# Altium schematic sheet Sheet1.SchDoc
size A4
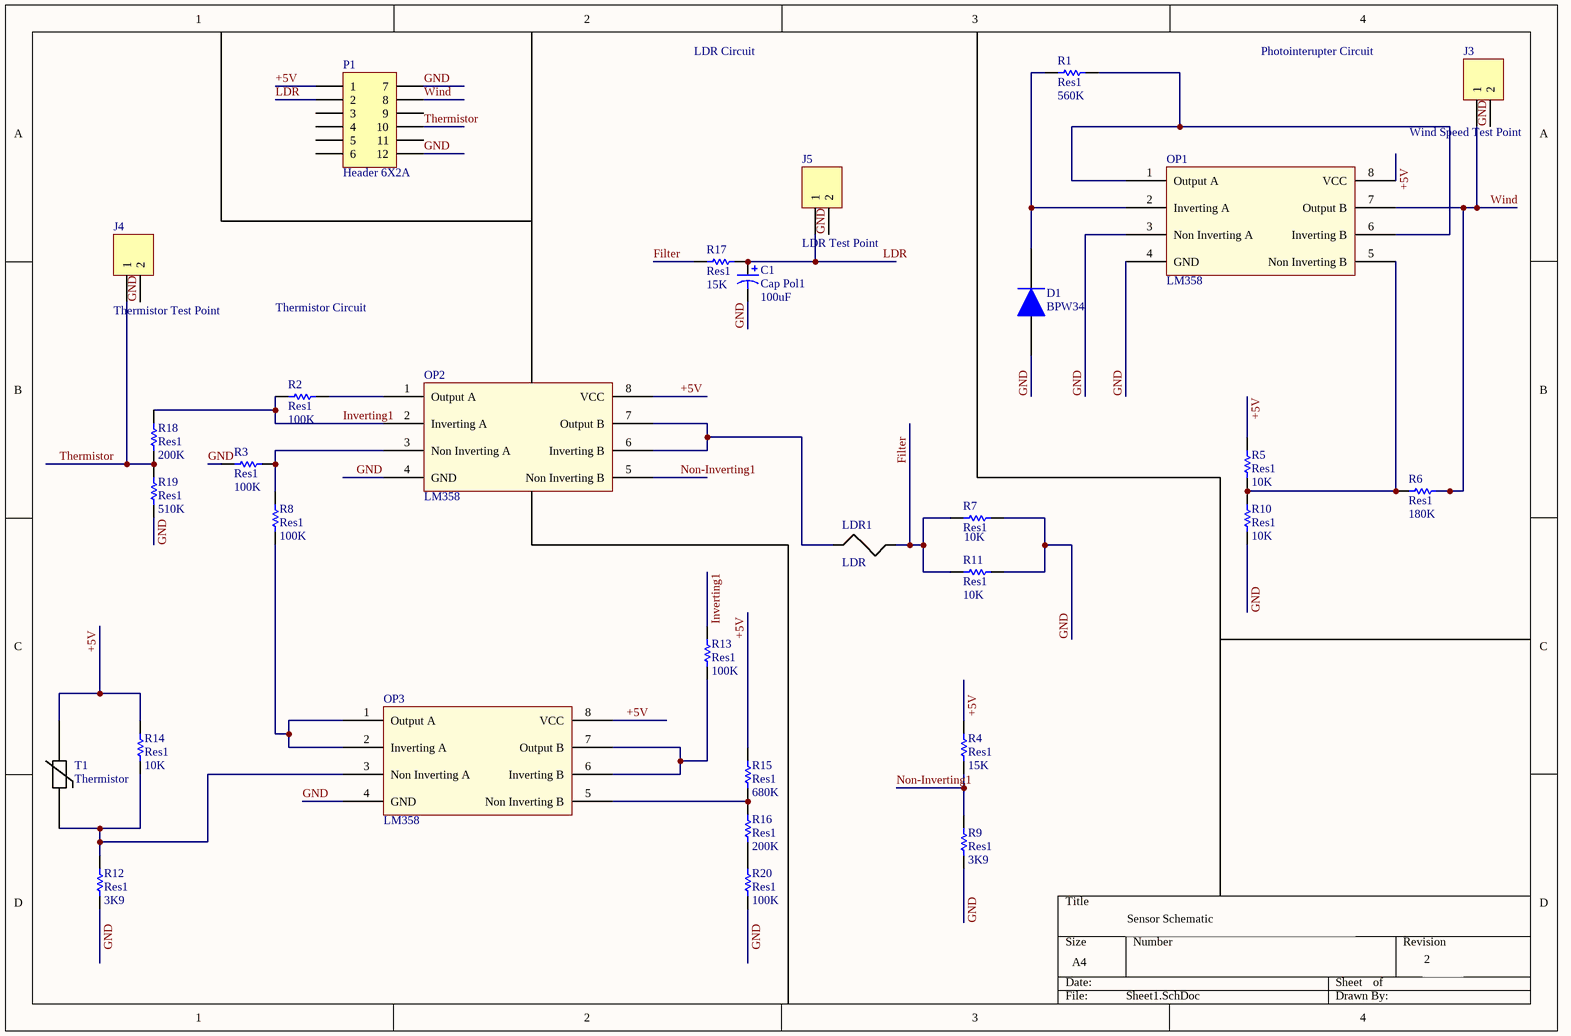
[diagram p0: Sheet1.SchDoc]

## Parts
C1  Cap Pol1  value 100uF  [PCBComponent_1]
D1  BPW34  [BPW34]
J3  Wind Speed Test Point  [HDR1X2]
J4  Thermistor Test Point  [HDR1X2]
J5  LDR Test Point  [HDR1X2]
LDR1  LDR  [PCBComponent_1]
OP1  LM358  [LM358]
OP2  LM358  [LM358]
OP3  LM358  [LM358]
P1  Header 6X2A  [HDR2X6_CEN]
R1  Res1  value 560K  [AXIAL-0.3]
R2  Res1  value 100K  [AXIAL-0.3]
R3  Res1  value 100K  [AXIAL-0.3]
R4  Res1  value 15K  [AXIAL-0.3]
R5  Res1  value 10K  [AXIAL-0.3]
R6  Res1  value 180K  [AXIAL-0.3]
R7  Res1  value 10K  [AXIAL-0.3]
R8  Res1  value 100K  [AXIAL-0.3]
R9  Res1  value 3K9  [AXIAL-0.3]
R10  Res1  value 10K  [AXIAL-0.3]
R11  Res1  value 10K  [AXIAL-0.3]
R12  Res1  value 3K9  [AXIAL-0.3]
R13  Res1  value 100K  [AXIAL-0.3]
R14  Res1  value 10K  [AXIAL-0.3]
R15  Res1  value 680K  [AXIAL-0.3]
R16  Res1  value 200K  [AXIAL-0.3]
R17  Res1  value 15K  [AXIAL-0.3]
R18  Res1  value 200K  [AXIAL-0.3]
R19  Res1  value 510K  [AXIAL-0.3]
R20  Res1  value 100K  [AXIAL-0.3]
T1  Thermistor  [PCBComponent_1]

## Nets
+5V: OP1.8(VCC) OP2.8(VCC) OP3.8(VCC) P1.1 R4.2 R5.2 R14.2 R15.2 T1.2
Filter: LDR1.2 R7.1 R11.1 R17.1
GND: C1.2 D1.2 J3.2 J4.2 J5.2 OP1.3(Non_Inverting_A) OP1.4(GND) OP2.4(GND) OP3.4(GND) P1.7 P1.12 R3.1 R7.2 R9.1 R10.1 R11.2 R12.1 R19.1 R20.1
Inverting1: OP2.2(Inverting_A) R2.1 R13.1 R18.2
LDR: C1.1 J5.1 P1.2 R17.2
Non-Inverting1: OP2.5(Non_Inverting_B) R4.1 R9.2
Thermistor: J4.1 P1.10 R18.1 R19.2
Wind: J3.1 OP1.7(Output_B) P1.8 R6.1
NetD1_1: D1.1 OP1.2(Inverting_A) R1.1
NetLDR1_1: LDR1.1 OP2.6(Inverting_B) OP2.7(Output_B)
NetOP1_1: OP1.1(Output_A) OP1.6(Inverting_B) R1.2
NetOP1_5: OP1.5(Non_Inverting_B) R5.1 R6.2 R10.2
NetOP2_1: OP2.1(Output_A) R2.2
NetOP2_3: OP2.3(Non_Inverting_A) R3.2 R8.2
NetOP3_1: OP3.1(Output_A) OP3.2(Inverting_A) R8.1
NetOP3_3: OP3.3(Non_Inverting_A) R12.2 R14.1 T1.1
NetOP3_5: OP3.5(Non_Inverting_B) R15.1 R16.2
NetOP3_6: OP3.6(Inverting_B) OP3.7(Output_B) R13.2
NetR16_1: R16.1 R20.2

Not connected (* = marked no-connect by the designer): P1 3 4 5 6 9 11

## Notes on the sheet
- LDR Circuit
- Photointerupter Circuit
- Thermistor Circuit
- Sensor Schematic
- 2

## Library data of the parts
C1 = Cap Pol1: Polarized Capacitor (Radial)
J3-J5 = Header 2: Header, 2-Pin
P1 = Header 6X2A: Header, 6-Pin, Dual row
R1-R20 = Res1: Resistor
